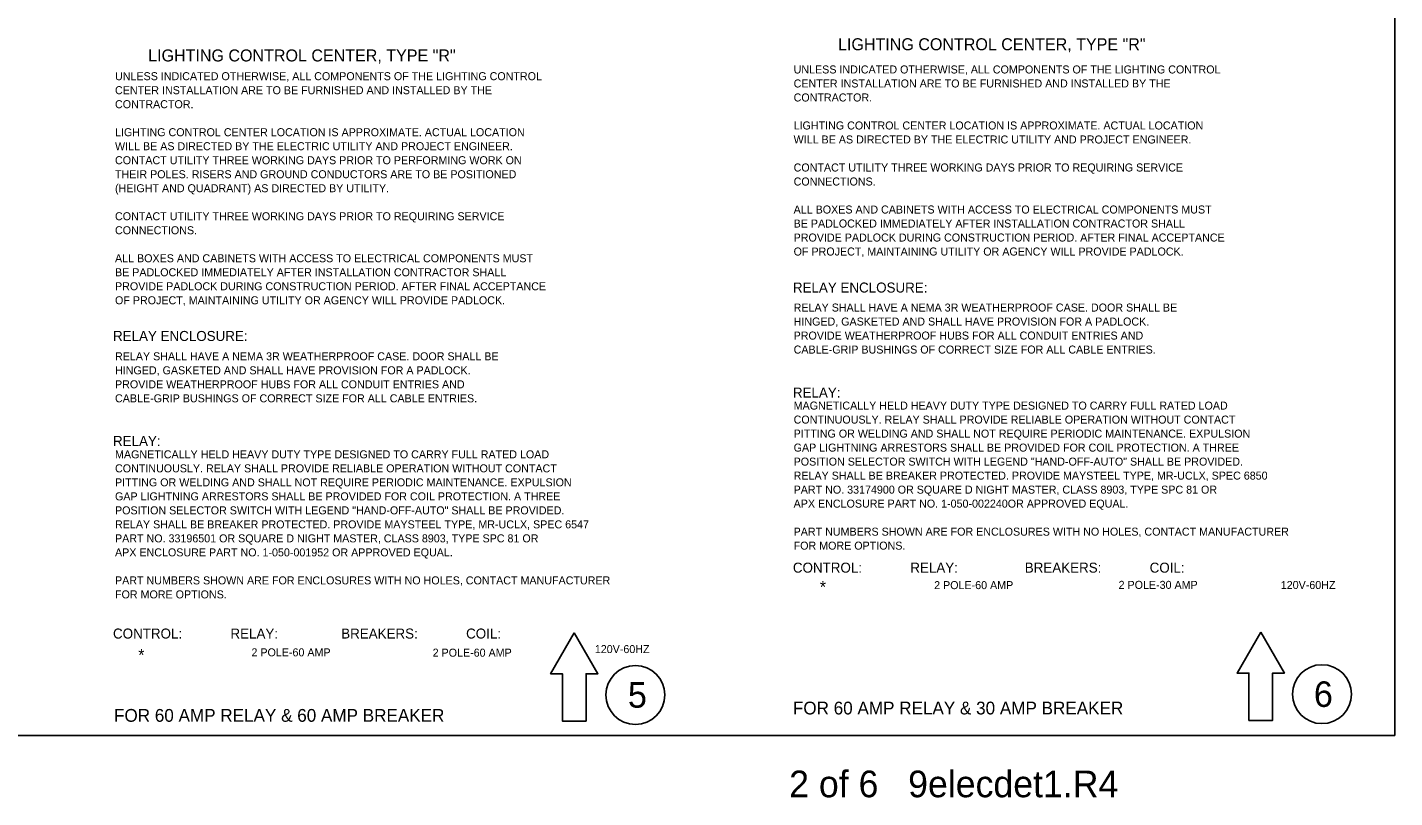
# Model space of a CAD drawing. Extents: x 100006 to 118406, y 96592 to 102182.
# Drawn here: x 106256 to 108306, y 99793 to 100948 of the extents above; entities that cross this region are included whole.
import ezdxf

# ---------------------------------------------------------------- set-up
doc = ezdxf.new("R2010")
doc.units = 0
for name, color, linetype in [('Default', 7, 'Continuous'), ('Level 7', 7, 'Continuous'), ('Level 9', 7, 'Continuous'), ('RD Standard Plans Active', 7, 'Continuous')]:
    doc.layers.add(name, color=color, linetype=linetype)

msp = doc.modelspace()

# ---------------------------------------------------------------- linework, layer by layer
at = {"layer": 'Default'}
msp.add_lwpolyline([(105106.4, 102085.7), (108306.1, 102085.7), (108306.1, 99886.1), (105106.4, 99886.1)], close=True, dxfattribs=at)
at = {"layer": 'Level 9'}
for points in [[(107075.9, 100039.9), (107040.4, 99978.4), (107058.1, 99978.4), (107058.1, 99907.5), (107093.6, 99907.5), (107093.6, 99978.4), (107111.3, 99978.4)], [(108105.3, 100041), (108069.8, 99979.6), (108087.5, 99979.6), (108087.5, 99908.6), (108123, 99908.6), (108123, 99979.6), (108140.7, 99979.6)]]:
    msp.add_lwpolyline(points, close=True, dxfattribs=at)
for centre in [(107167.6, 99946.8), (108197, 99947.9)]:
    msp.add_circle(centre, 44.2, dxfattribs=at)

# ---------------------------------------------------------------- texts
at = {"layer": 'Level 7'}
for s, height, p in [('LIGHTING CONTROL CENTER, TYPE "R"', 18, (107471.4, 100913.4)), ('LIGHTING CONTROL CENTER, TYPE "R"', 18, (106436.9, 100896.6)), ('UNLESS INDICATED OTHERWISE, ALL COMPONENTS OF THE LIGHTING CONTROL', 12, (106387.2, 100868.5)), ('UNLESS INDICATED OTHERWISE, ALL COMPONENTS OF THE LIGHTING CONTROL', 12, (107404.8, 100878.6)), ('CENTER INSTALLATION ARE TO BE FURNISHED AND INSTALLED BY THE', 12, (106387.2, 100847.5)), ('CENTER INSTALLATION ARE TO BE FURNISHED AND INSTALLED BY THE', 12, (107404.8, 100857.6)), ('CONTRACTOR.', 12, (106387.2, 100826.5)), ('CONTRACTOR.', 12, (107404.8, 100836.6)), ('LIGHTING CONTROL CENTER LOCATION IS APPROXIMATE. ACTUAL LOCATION', 12, (106387.2, 100784.5)), ('LIGHTING CONTROL CENTER LOCATION IS APPROXIMATE. ACTUAL LOCATION', 12, (107404.8, 100794.6)), ('WILL BE AS DIRECTED BY THE ELECTRIC UTILITY AND PROJECT ENGINEER.', 12, (106387.2, 100763.5)), ('WILL BE AS DIRECTED BY THE ELECTRIC UTILITY AND PROJECT ENGINEER.', 12, (107404.8, 100773.6)), ('CONTACT UTILITY THREE WORKING DAYS PRIOR TO PERFORMING WORK ON', 12, (106387.2, 100742.5)), ('THEIR POLES. RISERS AND GROUND CONDUCTORS ARE TO BE POSITIONED', 12, (106387.2, 100721.5)), ('CONTACT UTILITY THREE WORKING DAYS PRIOR TO REQUIRING SERVICE', 12, (107404.8, 100731.6)), ('(HEIGHT AND QUADRANT) AS DIRECTED BY UTILITY.', 12, (106387.2, 100700.5)), ('CONNECTIONS.', 12, (107404.8, 100710.6)), ('ALL BOXES AND CABINETS WITH ACCESS TO ELECTRICAL COMPONENTS MUST', 12, (107404.8, 100668.6)), ('CONTACT UTILITY THREE WORKING DAYS PRIOR TO REQUIRING SERVICE', 12, (106387.2, 100658.5)), ('BE PADLOCKED IMMEDIATELY AFTER INSTALLATION CONTRACTOR SHALL', 12, (107404.8, 100647.6)), ('CONNECTIONS.', 12, (106387.2, 100637.5)), ('PROVIDE PADLOCK DURING CONSTRUCTION PERIOD. AFTER FINAL ACCEPTANCE', 12, (107404.8, 100626.6)), ('OF PROJECT, MAINTAINING UTILITY OR AGENCY WILL PROVIDE PADLOCK.', 12, (107404.8, 100605.6)), ('ALL BOXES AND CABINETS WITH ACCESS TO ELECTRICAL COMPONENTS MUST', 12, (106387.2, 100595.5)), ('BE PADLOCKED IMMEDIATELY AFTER INSTALLATION CONTRACTOR SHALL', 12, (106387.2, 100574.5)), ('PROVIDE PADLOCK DURING CONSTRUCTION PERIOD. AFTER FINAL ACCEPTANCE', 12, (106387.2, 100553.5)), ('RELAY ENCLOSURE:', 15, (107403.7, 100550.1)), ('OF PROJECT, MAINTAINING UTILITY OR AGENCY WILL PROVIDE PADLOCK.', 12, (106387.2, 100532.5)), ('RELAY SHALL HAVE A NEMA 3R WEATHERPROOF CASE. DOOR SHALL BE', 12, (107404.8, 100521.6)), ('HINGED, GASKETED AND SHALL HAVE PROVISION FOR A PADLOCK.', 12, (107404.8, 100500.6)), ('RELAY ENCLOSURE:', 15, (106384.2, 100477.5)), ('PROVIDE WEATHERPROOF HUBS FOR ALL CONDUIT ENTRIES AND', 12, (107404.8, 100479.6)), ('CABLE-GRIP BUSHINGS OF CORRECT SIZE FOR ALL CABLE ENTRIES.', 12, (107404.8, 100458.6)), ('RELAY SHALL HAVE A NEMA 3R WEATHERPROOF CASE. DOOR SHALL BE', 12, (106387.2, 100448.5)), ('HINGED, GASKETED AND SHALL HAVE PROVISION FOR A PADLOCK.', 12, (106387.2, 100427.5)), ('PROVIDE WEATHERPROOF HUBS FOR ALL CONDUIT ENTRIES AND', 12, (106387.2, 100406.5)), ('RELAY:', 15, (107403.7, 100392.6)), ('CABLE-GRIP BUSHINGS OF CORRECT SIZE FOR ALL CABLE ENTRIES.', 12, (106387.2, 100385.5)), ('MAGNETICALLY HELD HEAVY DUTY TYPE DESIGNED TO CARRY FULL RATED LOAD ', 12, (107404.8, 100374.6)), ('CONTINUOUSLY. RELAY SHALL PROVIDE RELIABLE OPERATION WITHOUT CONTACT ', 12, (107404.8, 100353.6)), ('PITTING OR WELDING AND SHALL NOT REQUIRE PERIODIC MAINTENANCE. EXPULSION ', 12, (107404.8, 100332.6)), ('RELAY:', 15, (106384.2, 100320)), ('GAP LIGHTNING ARRESTORS SHALL BE PROVIDED FOR COIL PROTECTION. A THREE ', 12, (107404.8, 100311.6)), ('MAGNETICALLY HELD HEAVY DUTY TYPE DESIGNED TO CARRY FULL RATED LOAD ', 12, (106387.2, 100301.5)), ('POSITION SELECTOR SWITCH WITH LEGEND "HAND-OFF-AUTO" SHALL BE PROVIDED.  ', 12, (107404.8, 100290.6)), ('CONTINUOUSLY. RELAY SHALL PROVIDE RELIABLE OPERATION WITHOUT CONTACT ', 12, (106387.2, 100280.5)), ('RELAY SHALL BE BREAKER PROTECTED. PROVIDE MAYSTEEL TYPE, MR-UCLX, SPEC 6850 ', 12, (107404.8, 100269.6)), ('PITTING OR WELDING AND SHALL NOT REQUIRE PERIODIC MAINTENANCE. EXPULSION ', 12, (106387.2, 100259.5)), ('GAP LIGHTNING ARRESTORS SHALL BE PROVIDED FOR COIL PROTECTION. A THREE ', 12, (106387.2, 100238.5)), ('PART NO. 33174900 OR SQUARE D NIGHT MASTER, CLASS 8903, TYPE SPC 81 OR', 12, (107404.8, 100248.6)), ('POSITION SELECTOR SWITCH WITH LEGEND "HAND-OFF-AUTO" SHALL BE PROVIDED.  ', 12, (106387.2, 100217.5)), ('APX ENCLOSURE PART NO. 1-050-002240OR APPROVED EQUAL.', 12, (107404.8, 100227.6)), ('RELAY SHALL BE BREAKER PROTECTED. PROVIDE MAYSTEEL TYPE, MR-UCLX, SPEC 6547 ', 12, (106387.2, 100196.5)), ('PART NO. 33196501 OR SQUARE D NIGHT MASTER, CLASS 8903, TYPE SPC 81 OR', 12, (106387.2, 100175.5)), ('PART NUMBERS SHOWN ARE FOR ENCLOSURES WITH NO HOLES, CONTACT MANUFACTURER', 12, (107404.8, 100185.6)), ('APX ENCLOSURE PART NO. 1-050-001952 OR APPROVED EQUAL.', 12, (106387.2, 100154.5)), ('FOR MORE OPTIONS.  ', 12, (107404.8, 100164.6)), ('CONTROL:             RELAY:                  BREAKERS:             COIL:', 15, (107403.7, 100130.1)), ('PART NUMBERS SHOWN ARE FOR ENCLOSURES WITH NO HOLES, CONTACT MANUFACTURER', 12, (106387.2, 100112.5)), ('*', 18, (107444.1, 100099.7)), ('2 POLE-30 AMP', 12, (107892.1, 100105.8)), ('120V-60HZ', 12, (108135.3, 100105.6)), ('FOR MORE OPTIONS.  ', 12, (106387.2, 100091.5)), ('2 POLE-60 AMP', 12, (107615.5, 100105.4)), ('CONTROL:             RELAY:                 BREAKERS:             COIL:', 15, (106384.2, 100031.3)), ('*', 18, (106422, 99997.7)), ('2 POLE-60 AMP', 12, (106591.8, 100004.6)), ('2 POLE-60 AMP', 12, (106863.5, 100004.1)), ('120V-60HZ', 12, (107106.7, 100009.5))]:
    msp.add_text(s, height=height, dxfattribs=at).set_placement(p)
at = {"layer": 'Level 9'}
for s, height, p in [('5', 38.3, (107156.3, 99927.6)), ('6', 38.3, (108184.9, 99928.8)), ('FOR 60 AMP RELAY & 30 AMP BREAKER', 19.156, (107403.7, 99917.5)), ('FOR 60 AMP RELAY & 60 AMP BREAKER', 19.156, (106385.7, 99906.5))]:
    msp.add_text(s, height=height, dxfattribs=at).set_placement(p)
at = {"layer": 'RD Standard Plans Active'}
msp.add_text('     2 of 6   9elecdet1.R4', height=40, dxfattribs=at).set_placement((107323.8, 99793.3))

doc.saveas('drawing.dxf')
